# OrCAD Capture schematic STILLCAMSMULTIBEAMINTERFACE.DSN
size B; title: Ocean Imaging Sled Interface (Concept); rev: 2; note: OI001
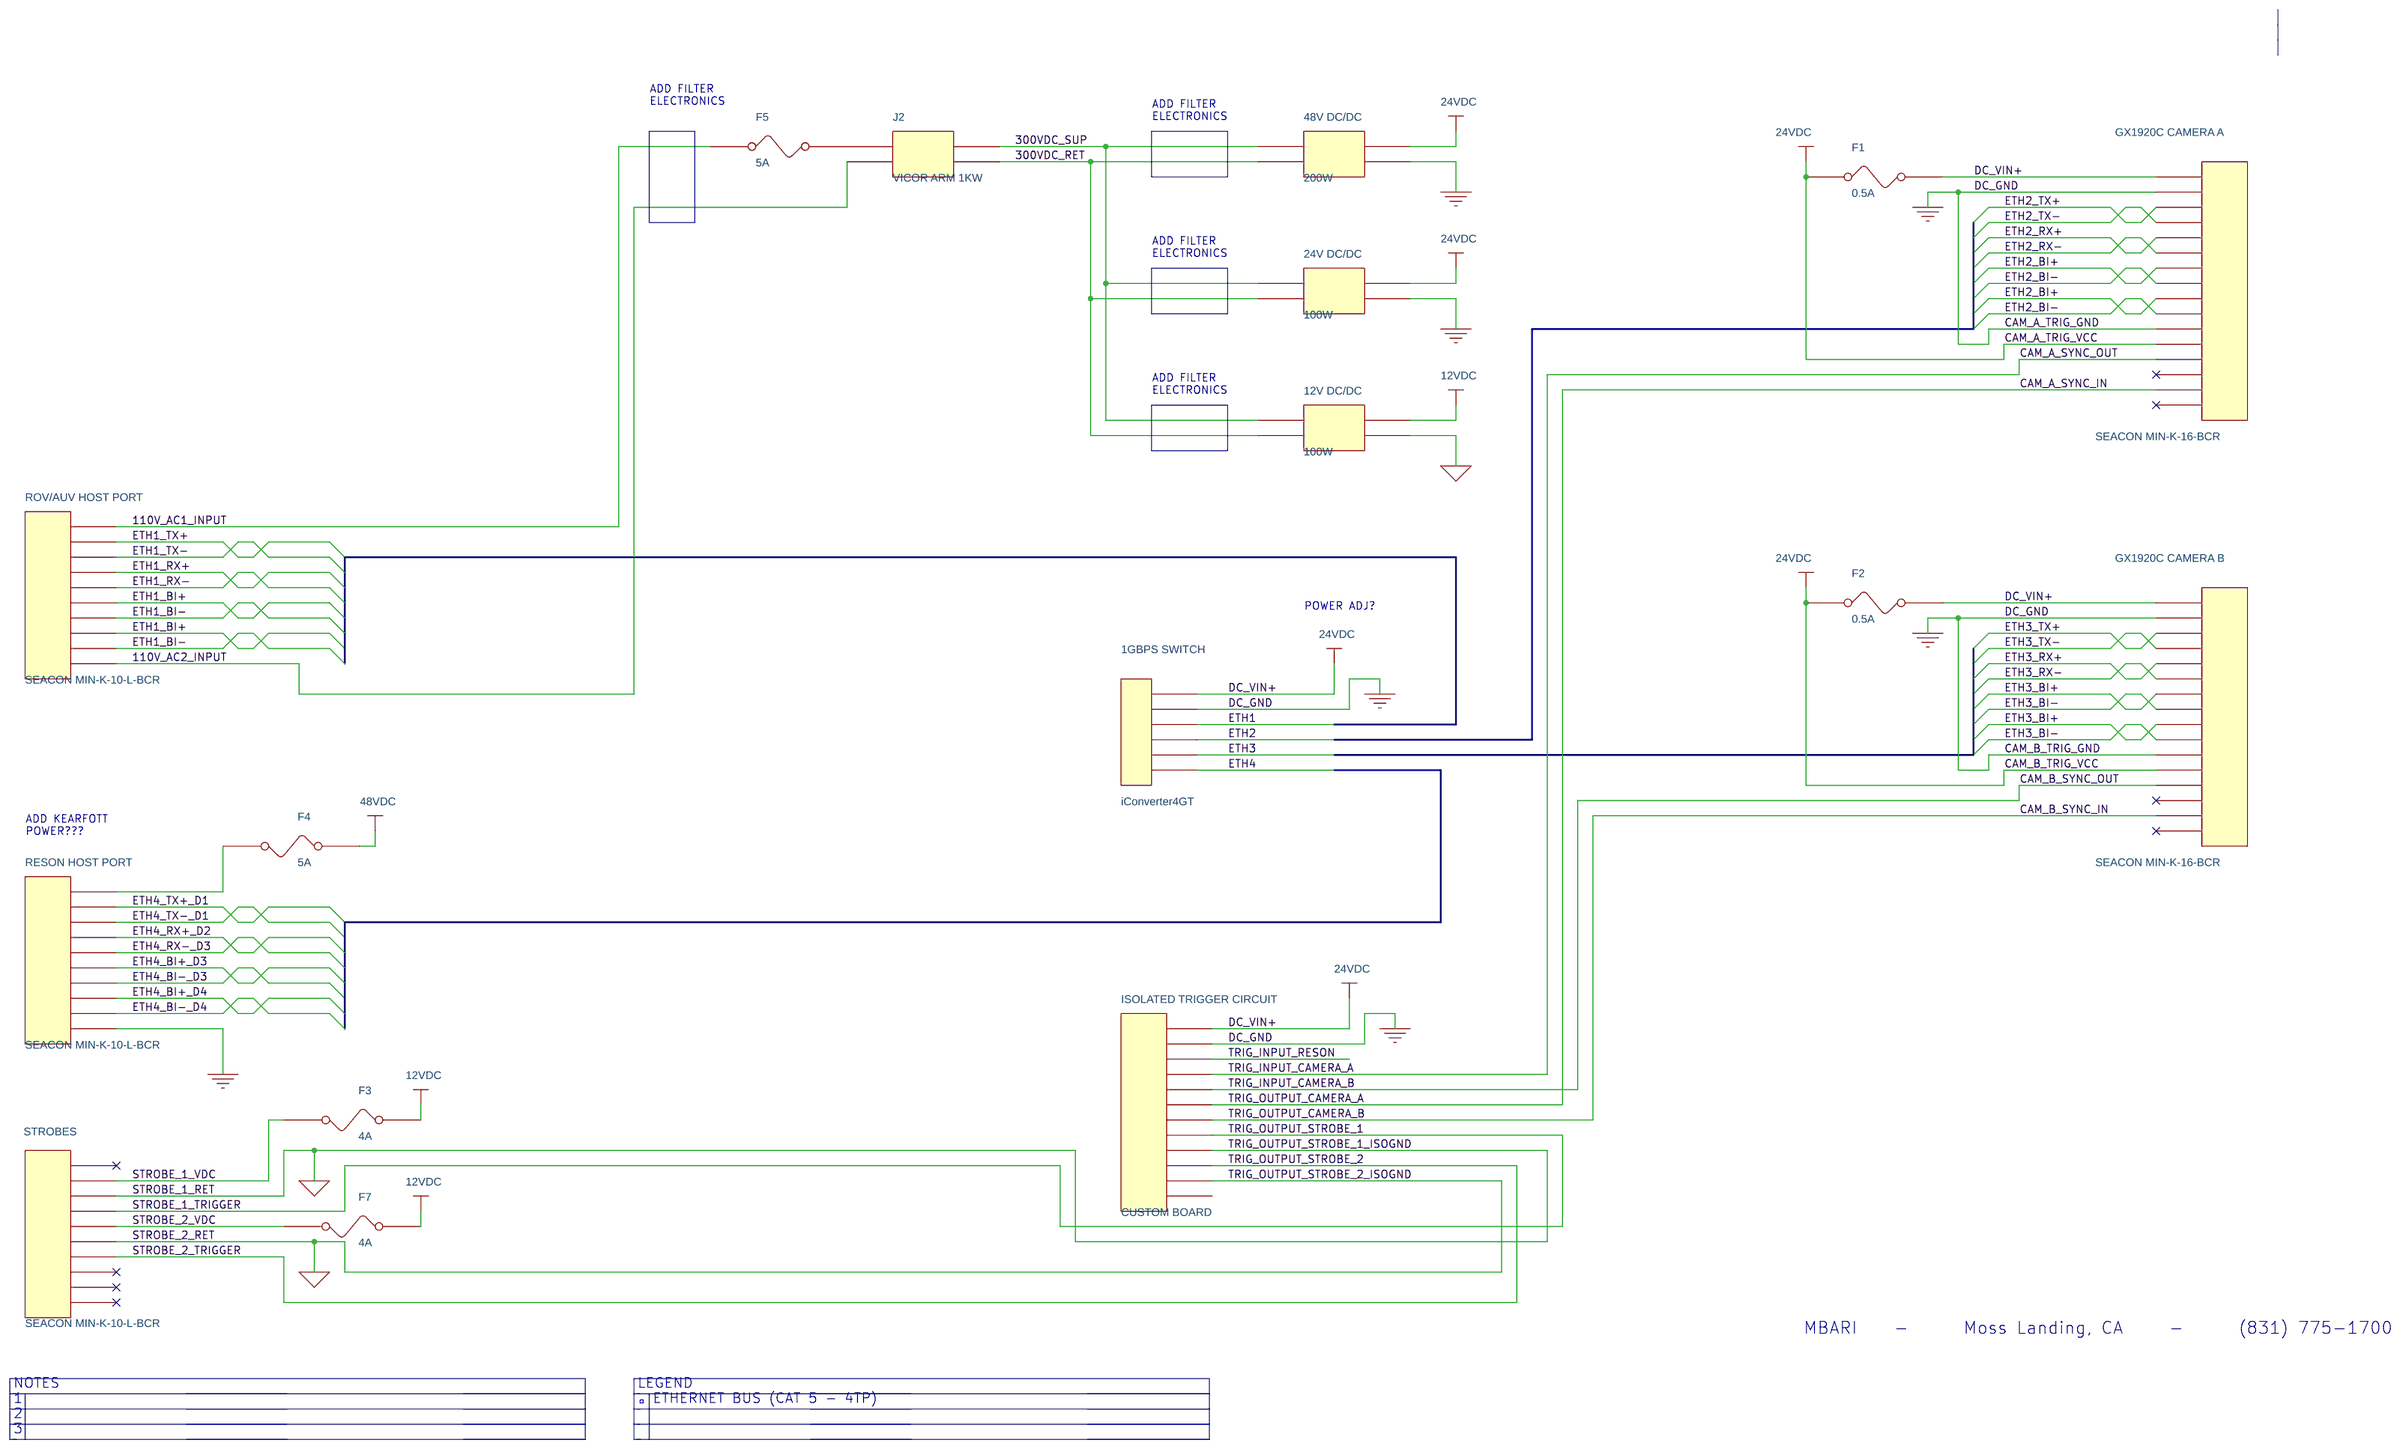
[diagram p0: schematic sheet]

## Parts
1GBPS SWITCH  iConverter4GT
12V DC/DC  100W
24V DC/DC  100W
48V DC/DC  200W
F1  0.5A
F2  0.5A
F3  4A
F4  5A
F5  5A
F7  4A
GX1920C CAMERA A  SEACON MIN-K-16-BCR
GX1920C CAMERA B  SEACON MIN-K-16-BCR
ISOLATED TRIGGER CIRCUIT  CUSTOM BOARD
J2  VICOR ARM 1KW
RESON HOST PORT  SEACON MIN-K-10-L-BCR
ROV/AUV HOST PORT  SEACON MIN-K-10-L-BCR
STROBES  SEACON MIN-K-10-L-BCR

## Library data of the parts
1GBPS SWITCH = CON6
12V DC/DC 24V DC/DC 48V DC/DC J2 = CON4A
F1-F5 F7 = FUSE
GX1920C CAMERA A GX1920C CAMERA B = CON16
ISOLATED TRIGGER CIRCUIT = CON12
RESON HOST PORT ROV/AUV HOST PORT STROBES = CON10

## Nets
12VDC: 12V DC/DC.2 F3.1 F7.1
24VDC: 1GBPS SWITCH.1 24V DC/DC.2 48V DC/DC.2 F1.1 F1.2 F2.1 F2.2 GX1920C CAMERA A.1 GX1920C CAMERA A.12 GX1920C CAMERA B.1 GX1920C CAMERA B.12 ISOLATED TRIGGER CIRCUIT.1
48VDC: F4.1
110V_AC1_INPUT: F5.1 ROV/AUV HOST PORT.1
110V_AC2_INPUT: J2.3 ROV/AUV HOST PORT.10
300VDC_RET: 12V DC/DC.3 24V DC/DC.3 48V DC/DC.3 J2.4
300VDC_SUP: 12V DC/DC.1 24V DC/DC.1 48V DC/DC.1 J2.2
GND_ISO: 12V DC/DC.4 ISOLATED TRIGGER CIRCUIT.9 ISOLATED TRIGGER CIRCUIT.11 STROBES.3 STROBES.6
GND_POWER: 1GBPS SWITCH.2 24V DC/DC.4 48V DC/DC.4 GX1920C CAMERA A.2 GX1920C CAMERA A.11 GX1920C CAMERA B.2 GX1920C CAMERA B.11 ISOLATED TRIGGER CIRCUIT.2 RESON HOST PORT.10
CAM_A_SYNC_IN: GX1920C CAMERA A.15 ISOLATED TRIGGER CIRCUIT.6
CAM_A_SYNC_OUT: GX1920C CAMERA A.13 ISOLATED TRIGGER CIRCUIT.4
CAM_B_SYNC_IN: GX1920C CAMERA B.15 ISOLATED TRIGGER CIRCUIT.7
CAM_B_SYNC_OUT: GX1920C CAMERA B.13 ISOLATED TRIGGER CIRCUIT.5
ETH1: 1GBPS SWITCH.3
ETH1_BI+: ROV/AUV HOST PORT.6 ROV/AUV HOST PORT.8
ETH1_BI-: ROV/AUV HOST PORT.7 ROV/AUV HOST PORT.9
ETH1_RX+: ROV/AUV HOST PORT.4
ETH1_RX-: ROV/AUV HOST PORT.5
ETH1_TX+: ROV/AUV HOST PORT.2
ETH1_TX-: ROV/AUV HOST PORT.3
ETH2: 1GBPS SWITCH.4
ETH2_BI+: GX1920C CAMERA A.7 GX1920C CAMERA A.9
ETH2_BI-: GX1920C CAMERA A.8 GX1920C CAMERA A.10
ETH2_RX+: GX1920C CAMERA A.5
ETH2_RX-: GX1920C CAMERA A.6
ETH2_TX+: GX1920C CAMERA A.3
ETH2_TX-: GX1920C CAMERA A.4
ETH3: 1GBPS SWITCH.5
ETH3_BI+: GX1920C CAMERA B.7 GX1920C CAMERA B.9
ETH3_BI-: GX1920C CAMERA B.8 GX1920C CAMERA B.10
ETH3_RX+: GX1920C CAMERA B.5
ETH3_RX-: GX1920C CAMERA B.6
ETH3_TX+: GX1920C CAMERA B.3
ETH3_TX-: GX1920C CAMERA B.4
ETH4: 1GBPS SWITCH.6
ETH4_BI+_D3: RESON HOST PORT.6
ETH4_BI+_D4: RESON HOST PORT.8
ETH4_BI-_D3: RESON HOST PORT.7
ETH4_BI-_D4: RESON HOST PORT.9
ETH4_RX+_D2: RESON HOST PORT.4
ETH4_RX-_D3: RESON HOST PORT.5
ETH4_TX+_D1: RESON HOST PORT.2
ETH4_TX-_D1: RESON HOST PORT.3
STROBE_1_TRIGGER: ISOLATED TRIGGER CIRCUIT.8 STROBES.4
STROBE_1_VDC: F3.2 STROBES.2
STROBE_2_TRIGGER: ISOLATED TRIGGER CIRCUIT.10 STROBES.7
STROBE_2_VDC: F7.2 STROBES.5
TRIG_INPUT_RESON: ISOLATED TRIGGER CIRCUIT.3
N82525: F4.2 RESON HOST PORT.1
N89374: F5.2 J2.1

Not connected (* = marked no-connect by the designer): GX1920C CAMERA A 14* 16*; GX1920C CAMERA B 14* 16*; ISOLATED TRIGGER CIRCUIT 12; STROBES 1* 8* 9* 10*

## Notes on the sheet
- ADD FILTER
  ELECTRONICS
- ADD FILTER
  ELECTRONICS
- ADD FILTER
  ELECTRONICS
- ADD FILTER
  ELECTRONICS
- POWER ADJ?
- ADD KEARFOTT
  POWER???
- MBARI    -      Moss Landing, CA     -      (831) 775-1700
- NOTES
- LEGEND
- 1
- ETHERNET BUS (CAT 5 - 4TP)
- 2
- 3
